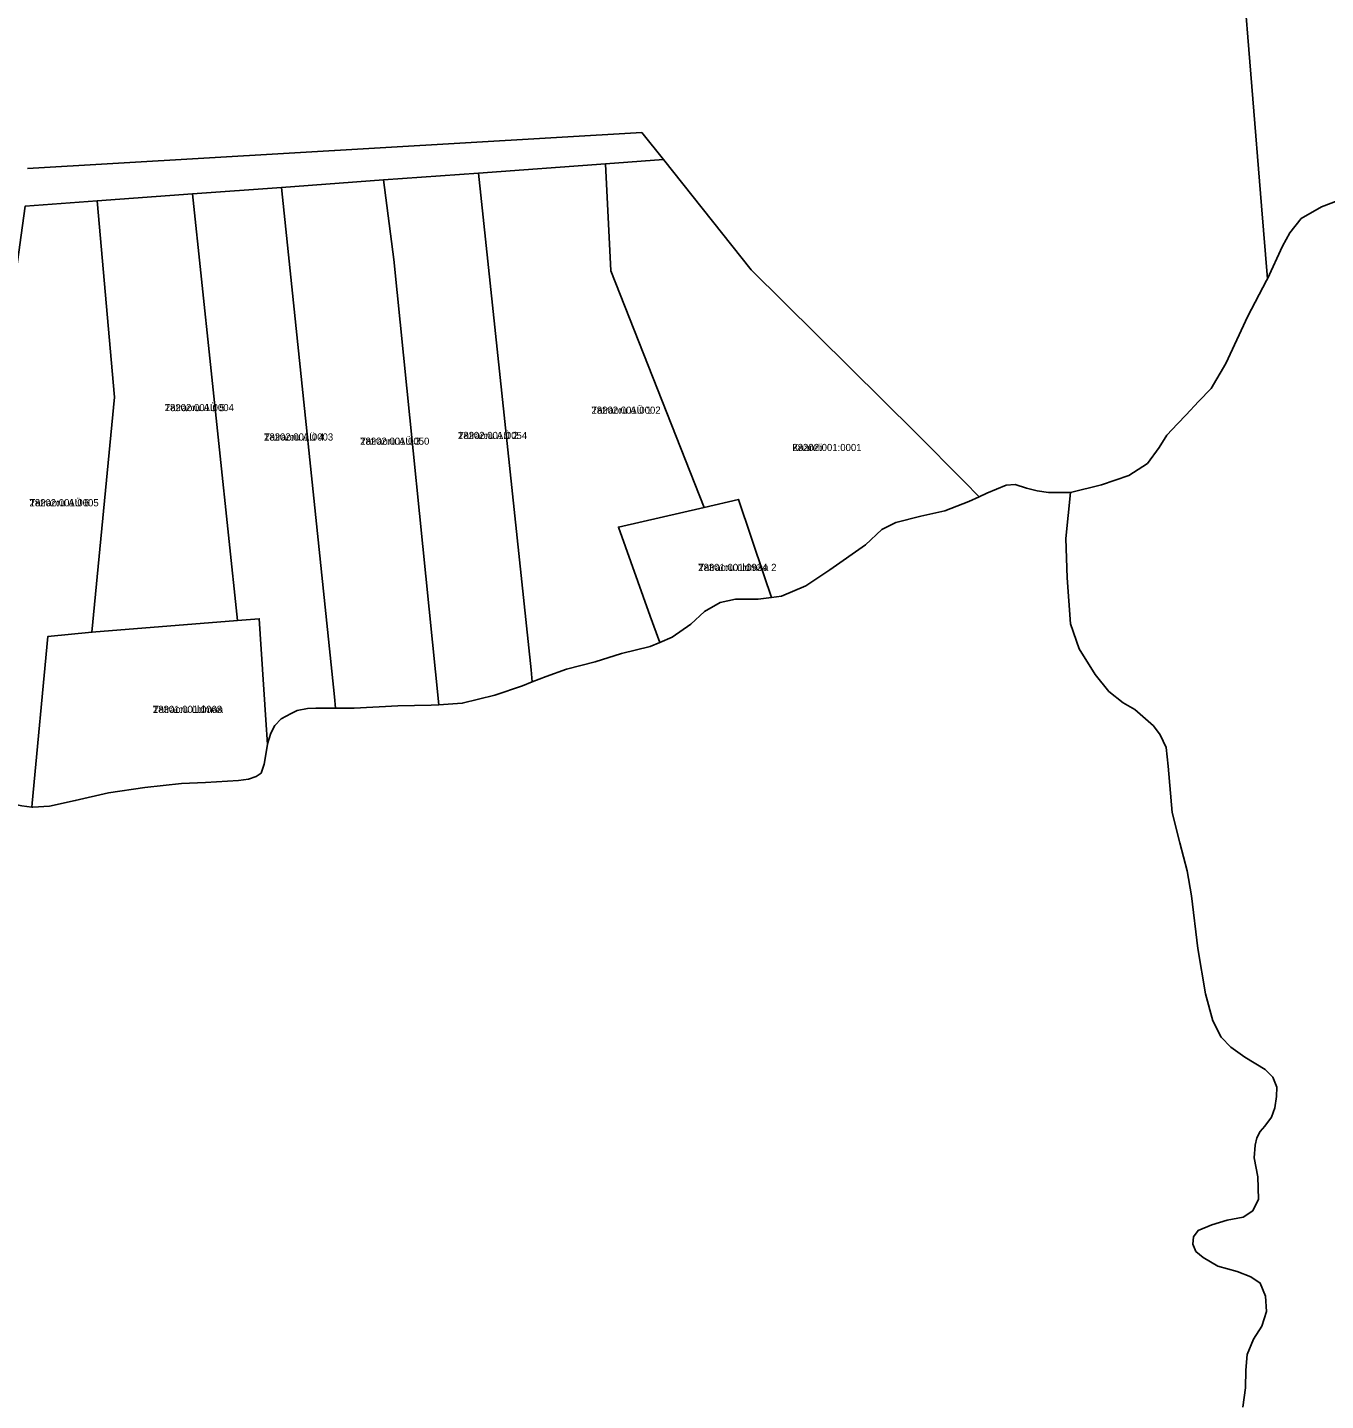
# Model space of a CAD drawing. Extents: x 647845 to 668483, y 6445298 to 6473683.
# Drawn here: x 655639.8 to 655911.9, y 6459640.6 to 6459928.3 of the extents above; entities that cross this region are included whole.
import ezdxf

# ---------------------------------------------------------------- set-up
doc = ezdxf.new("R2010")
doc.units = 0
for name, color, linetype in [('L_AADRESS', 7, 'Continuous'), ('PIIR', 7, 'Continuous'), ('TUNNUS', 7, 'Continuous')]:
    doc.layers.add(name, color=color, linetype=linetype)

msp = doc.modelspace()

# ---------------------------------------------------------------- linework, layer by layer
at = {"layer": 'PIIR'}
for points in [[(655892.35, 6459966.03), (655898.43, 6459890.95), (655899.67, 6459875.61), (655899.52, 6459875.28), (655895.6, 6459867.81), (655890.96, 6459857.9), (655887.9, 6459852.64), (655885.21, 6459849.95), (655882.64, 6459847.13), (655880.85, 6459845.22), (655878.6, 6459842.9), (655877.02, 6459840.28), (655874.57, 6459836.97), (655870.66, 6459834.4), (655864.91, 6459832.44), (655858.42, 6459830.85), (655853.81, 6459830.88), (655851.4, 6459831.22), (655849.2, 6459831.79), (655846.83, 6459832.51), (655844.92, 6459832.4), (655840.88, 6459830.69), (655839.26, 6459829.95), (655836.1, 6459833.14), (655825.99, 6459843.36), (655791.51, 6459877.52), (655773.1, 6459900.64), (655768.57, 6459906.32), (655639.81, 6459898.78)], [(655915.99, 6459892.62), (655911.04, 6459890.76), (655906.78, 6459888.28), (655904.41, 6459885.31), (655902.81, 6459882.51), (655899.67, 6459875.61), (655898.43, 6459890.95), (655892.35, 6459966.03)], [(655639.81, 6459898.78), (655768.57, 6459906.32), (655773.1, 6459900.64), (655760.99, 6459899.77), (655734.37, 6459897.81), (655714.45, 6459896.37), (655693.06, 6459894.8), (655674.39, 6459893.42), (655654.46, 6459891.98), (655639.35, 6459890.87)], [(655894.56, 6459639.22), (655895.11, 6459643.27), (655895.19, 6459646.92), (655895.42, 6459650.26), (655896.77, 6459653.43), (655898.51, 6459656.13), (655899.46, 6459659.23), (655899.3, 6459662.48), (655898.19, 6459665.18), (655896.2, 6459666.53), (655893.34, 6459667.64), (655889.3, 6459668.75), (655886.2, 6459670.57), (655884.69, 6459671.84), (655884.05, 6459673.35), (655884.21, 6459674.85), (655885.16, 6459676.2), (655888.02, 6459677.4), (655891.27, 6459678.35), (655894.61, 6459678.99), (655896.59, 6459680.34), (655897.78, 6459682.8), (655897.7, 6459687.48), (655896.9, 6459691.45), (655897.09, 6459694.08), (655897.48, 6459695.66), (655898.16, 6459696.95), (655899.11, 6459698.08), (655900.52, 6459699.99), (655901.25, 6459701.91), (655901.59, 6459704.27), (655901.64, 6459706.24), (655900.79, 6459708.33), (655899.21, 6459709.92), (655894.94, 6459712.5), (655891.98, 6459714.62), (655889.99, 6459716.75), (655888.27, 6459720.12), (655886.69, 6459725.8), (655885.09, 6459735.34), (655883.75, 6459746.35), (655882.84, 6459751.59), (655881.3, 6459757.48), (655879.71, 6459763.84), (655878.85, 6459773.5), (655878.49, 6459777.41), (655877.18, 6459780.08), (655875.8, 6459781.94), (655871.88, 6459785.36), (655869.47, 6459786.81), (655866.46, 6459789.13), (655863.56, 6459792.69), (655860.26, 6459798.07), (655858.43, 6459803.33), (655857.69, 6459812.99), (655857.45, 6459821.19), (655858.42, 6459830.85), (655864.91, 6459832.44), (655870.66, 6459834.4), (655874.57, 6459836.97), (655877.02, 6459840.28), (655878.6, 6459842.9), (655880.85, 6459845.22), (655882.64, 6459847.13), (655885.21, 6459849.95), (655887.9, 6459852.64), (655890.96, 6459857.9), (655895.6, 6459867.81), (655899.52, 6459875.28), (655899.67, 6459875.61), (655902.81, 6459882.51), (655904.41, 6459885.31), (655906.78, 6459888.28), (655911.04, 6459890.76), (655915.99, 6459892.62)], [(655638.64, 6459765.23), (655640.72, 6459764.95), (655640.94, 6459764.92), (655644.44, 6459765.16), (655649.84, 6459766.31), (655656.81, 6459767.91), (655664.39, 6459769.01), (655672.1, 6459769.87), (655677.11, 6459770.12), (655684.05, 6459770.5), (655686.16, 6459770.82), (655687.75, 6459771.35), (655688.77, 6459772.08), (655689.39, 6459773.94), (655690.1, 6459778.05), (655690.13, 6459778.23), (655690.81, 6459780.4), (655691.66, 6459782.04), (655692.98, 6459783.42), (655695.06, 6459784.57), (655696.37, 6459785.16), (655698.48, 6459785.59), (655700.28, 6459785.7), (655704.38, 6459785.68), (655708.26, 6459785.66), (655717.43, 6459786.15), (655724.4, 6459786.28), (655726.02, 6459786.38), (655730.93, 6459786.7), (655737.78, 6459788.42), (655743.53, 6459790.38), (655745.62, 6459791.2), (655748.54, 6459792.34), (655752.82, 6459793.81), (655758.81, 6459795.4), (655764.32, 6459797.12), (655770.31, 6459798.59), (655772.33, 6459799.44), (655774.96, 6459800.55), (655778.87, 6459803.25), (655781.69, 6459805.94), (655784.99, 6459807.78), (655788.17, 6459808.51), (655792.94, 6459808.51), (655795.72, 6459808.86), (655797.83, 6459809.13), (655802.97, 6459811.33), (655807.98, 6459814.64), (655815.44, 6459819.91), (655818.87, 6459823.09), (655821.8, 6459824.56), (655827.06, 6459825.91), (655832.08, 6459827.01), (655837.09, 6459828.97), (655839.26, 6459829.95), (655840.88, 6459830.69), (655844.92, 6459832.4), (655846.83, 6459832.51), (655849.2, 6459831.79), (655851.4, 6459831.22), (655853.81, 6459830.88), (655858.42, 6459830.85), (655857.45, 6459821.19), (655857.69, 6459812.99), (655858.43, 6459803.33), (655860.26, 6459798.07), (655863.56, 6459792.69), (655866.46, 6459789.13), (655869.47, 6459786.81), (655871.88, 6459785.36), (655875.8, 6459781.94), (655877.18, 6459780.08), (655878.49, 6459777.41), (655878.85, 6459773.5), (655879.71, 6459763.84), (655881.3, 6459757.48), (655882.84, 6459751.59), (655883.75, 6459746.35), (655885.09, 6459735.34), (655886.69, 6459725.8), (655888.27, 6459720.12), (655889.99, 6459716.75), (655891.98, 6459714.62), (655894.94, 6459712.5), (655899.21, 6459709.92), (655900.79, 6459708.33), (655901.64, 6459706.24), (655901.59, 6459704.27), (655901.25, 6459701.91), (655900.52, 6459699.99), (655899.11, 6459698.08), (655898.16, 6459696.95), (655897.48, 6459695.66), (655897.09, 6459694.08), (655896.9, 6459691.45), (655897.7, 6459687.48), (655897.78, 6459682.8), (655896.59, 6459680.34), (655894.61, 6459678.99), (655891.27, 6459678.35), (655888.02, 6459677.4), (655885.16, 6459676.2), (655884.21, 6459674.85), (655884.05, 6459673.35), (655884.69, 6459671.84), (655886.2, 6459670.57), (655889.3, 6459668.75), (655893.34, 6459667.64), (655896.2, 6459666.53), (655898.19, 6459665.18), (655899.3, 6459662.48), (655899.46, 6459659.23), (655898.51, 6459656.13), (655896.77, 6459653.43), (655895.42, 6459650.26), (655895.19, 6459646.92), (655895.11, 6459643.27), (655894.56, 6459639.22)]]:
    msp.add_lwpolyline(points, dxfattribs=at)
for points in [[(655762.07, 6459877.33), (655781.65, 6459827.75), (655763.65, 6459823.63), (655770.35, 6459804.95), (655772.33, 6459799.44), (655770.31, 6459798.59), (655764.32, 6459797.12), (655758.81, 6459795.4), (655752.82, 6459793.81), (655748.54, 6459792.34), (655745.62, 6459791.2), (655745.37, 6459793.67), (655734.37, 6459897.81), (655760.99, 6459899.77)], [(655791.51, 6459877.52), (655825.99, 6459843.36), (655836.1, 6459833.14), (655839.26, 6459829.95), (655837.09, 6459828.97), (655832.08, 6459827.01), (655827.06, 6459825.91), (655821.8, 6459824.56), (655818.87, 6459823.09), (655815.44, 6459819.91), (655807.98, 6459814.64), (655802.97, 6459811.33), (655797.83, 6459809.13), (655795.72, 6459808.86), (655794.2, 6459813.39), (655788.84, 6459829.4), (655781.65, 6459827.75), (655762.07, 6459877.33), (655760.99, 6459899.77), (655773.1, 6459900.64)], [(655745.37, 6459793.67), (655745.62, 6459791.2), (655743.53, 6459790.38), (655737.78, 6459788.42), (655730.93, 6459786.7), (655726.02, 6459786.38), (655716.57, 6459879.69), (655714.45, 6459896.37), (655734.37, 6459897.81)], [(655704.14, 6459788.03), (655704.38, 6459785.68), (655700.28, 6459785.7), (655698.48, 6459785.59), (655696.37, 6459785.16), (655695.06, 6459784.57), (655692.98, 6459783.42), (655691.66, 6459782.04), (655690.81, 6459780.4), (655690.13, 6459778.23), (655690.1, 6459778.05), (655689.76, 6459783.22), (655688.38, 6459804.41), (655683.83, 6459804.07), (655674.39, 6459893.42), (655693.06, 6459894.8)], [(655716.57, 6459879.69), (655726.02, 6459786.38), (655724.4, 6459786.28), (655717.43, 6459786.15), (655708.26, 6459785.66), (655704.38, 6459785.68), (655704.14, 6459788.03), (655693.06, 6459894.8), (655714.45, 6459896.37)], [(655658.06, 6459850.82), (655653.33, 6459801.58), (655644.06, 6459800.68), (655640.79, 6459765.73), (655640.72, 6459764.95), (655638.64, 6459765.23), (655633.57, 6459766.23), (655623.78, 6459768.54), (655622.42, 6459768.87), (655622.68, 6459770.73), (655639.35, 6459890.87), (655654.46, 6459891.98)], [(655683.83, 6459804.07), (655653.33, 6459801.58), (655658.06, 6459850.82), (655654.46, 6459891.98), (655674.39, 6459893.42)], [(655774.96, 6459800.55), (655772.33, 6459799.44), (655770.35, 6459804.95), (655763.65, 6459823.63), (655781.65, 6459827.75), (655788.84, 6459829.4), (655794.2, 6459813.39), (655795.72, 6459808.86), (655792.94, 6459808.51), (655788.17, 6459808.51), (655784.99, 6459807.78), (655781.69, 6459805.94), (655778.87, 6459803.25)], [(655688.38, 6459804.41), (655689.76, 6459783.22), (655690.1, 6459778.05), (655689.39, 6459773.94), (655688.77, 6459772.08), (655687.75, 6459771.35), (655686.16, 6459770.82), (655684.05, 6459770.5), (655677.11, 6459770.12), (655672.1, 6459769.87), (655664.39, 6459769.01), (655656.81, 6459767.91), (655649.84, 6459766.31), (655644.44, 6459765.16), (655640.94, 6459764.92), (655640.72, 6459764.95), (655640.79, 6459765.73), (655644.06, 6459800.68), (655653.33, 6459801.58), (655683.83, 6459804.07)]]:
    msp.add_lwpolyline(points, close=True, dxfattribs=at)

# ---------------------------------------------------------------- texts
at = {"layer": 'L_AADRESS'}
for s, p in [('Tatraoru AÜ 5', (655668.58, 6459847.91)), ('Tatraoru AÜ 1', (655758.01, 6459847.37)), ('Tatraoru AÜ 4', (655689.39, 6459841.75)), ('Tatraoru AÜ 3', (655709.54, 6459840.87)), ('Tatraoru AÜ 2', (655730.04, 6459842.07)), ('Kaareli', (655800.12, 6459839.55)), ('Tatraoru AÜ 6', (655640.24, 6459827.97)), ('Tatraoru üldmaa 2', (655780.4, 6459814.42)), ('Tatraoru üldmaa', (655666.11, 6459784.67))]:
    msp.add_text(s, height=1.5, dxfattribs=at).set_placement(p)
at = {"layer": 'TUNNUS'}
for s, p in [('28202:001:0004', (655668.58, 6459847.91)), ('28202:001:0002', (655758.01, 6459847.37)), ('28202:001:0003', (655689.39, 6459841.75)), ('28202:001:0050', (655709.54, 6459840.87)), ('28202:001:0054', (655730.04, 6459842.07)), ('28202:001:0001', (655800.12, 6459839.55)), ('28202:001:0005', (655640.24, 6459827.97)), ('28301:001:0934', (655780.4, 6459814.42)), ('28301:001:0068', (655666.11, 6459784.67))]:
    msp.add_text(s, height=1.5, dxfattribs=at).set_placement(p)

doc.saveas('drawing.dxf')
